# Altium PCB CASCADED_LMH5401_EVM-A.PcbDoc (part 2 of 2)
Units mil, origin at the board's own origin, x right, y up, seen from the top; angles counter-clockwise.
Board outline 1606 x 1500 mil, 6 copper layers (Top Layer L1, Layer 2 GND L2, Layer 3 V+ L3, Layer 4 V- L4, Layer 5 GND L5, Bottom Layer L6), stack 56.6 mil thick; 98 components, 31 nets, 225 pads, 397 vias.
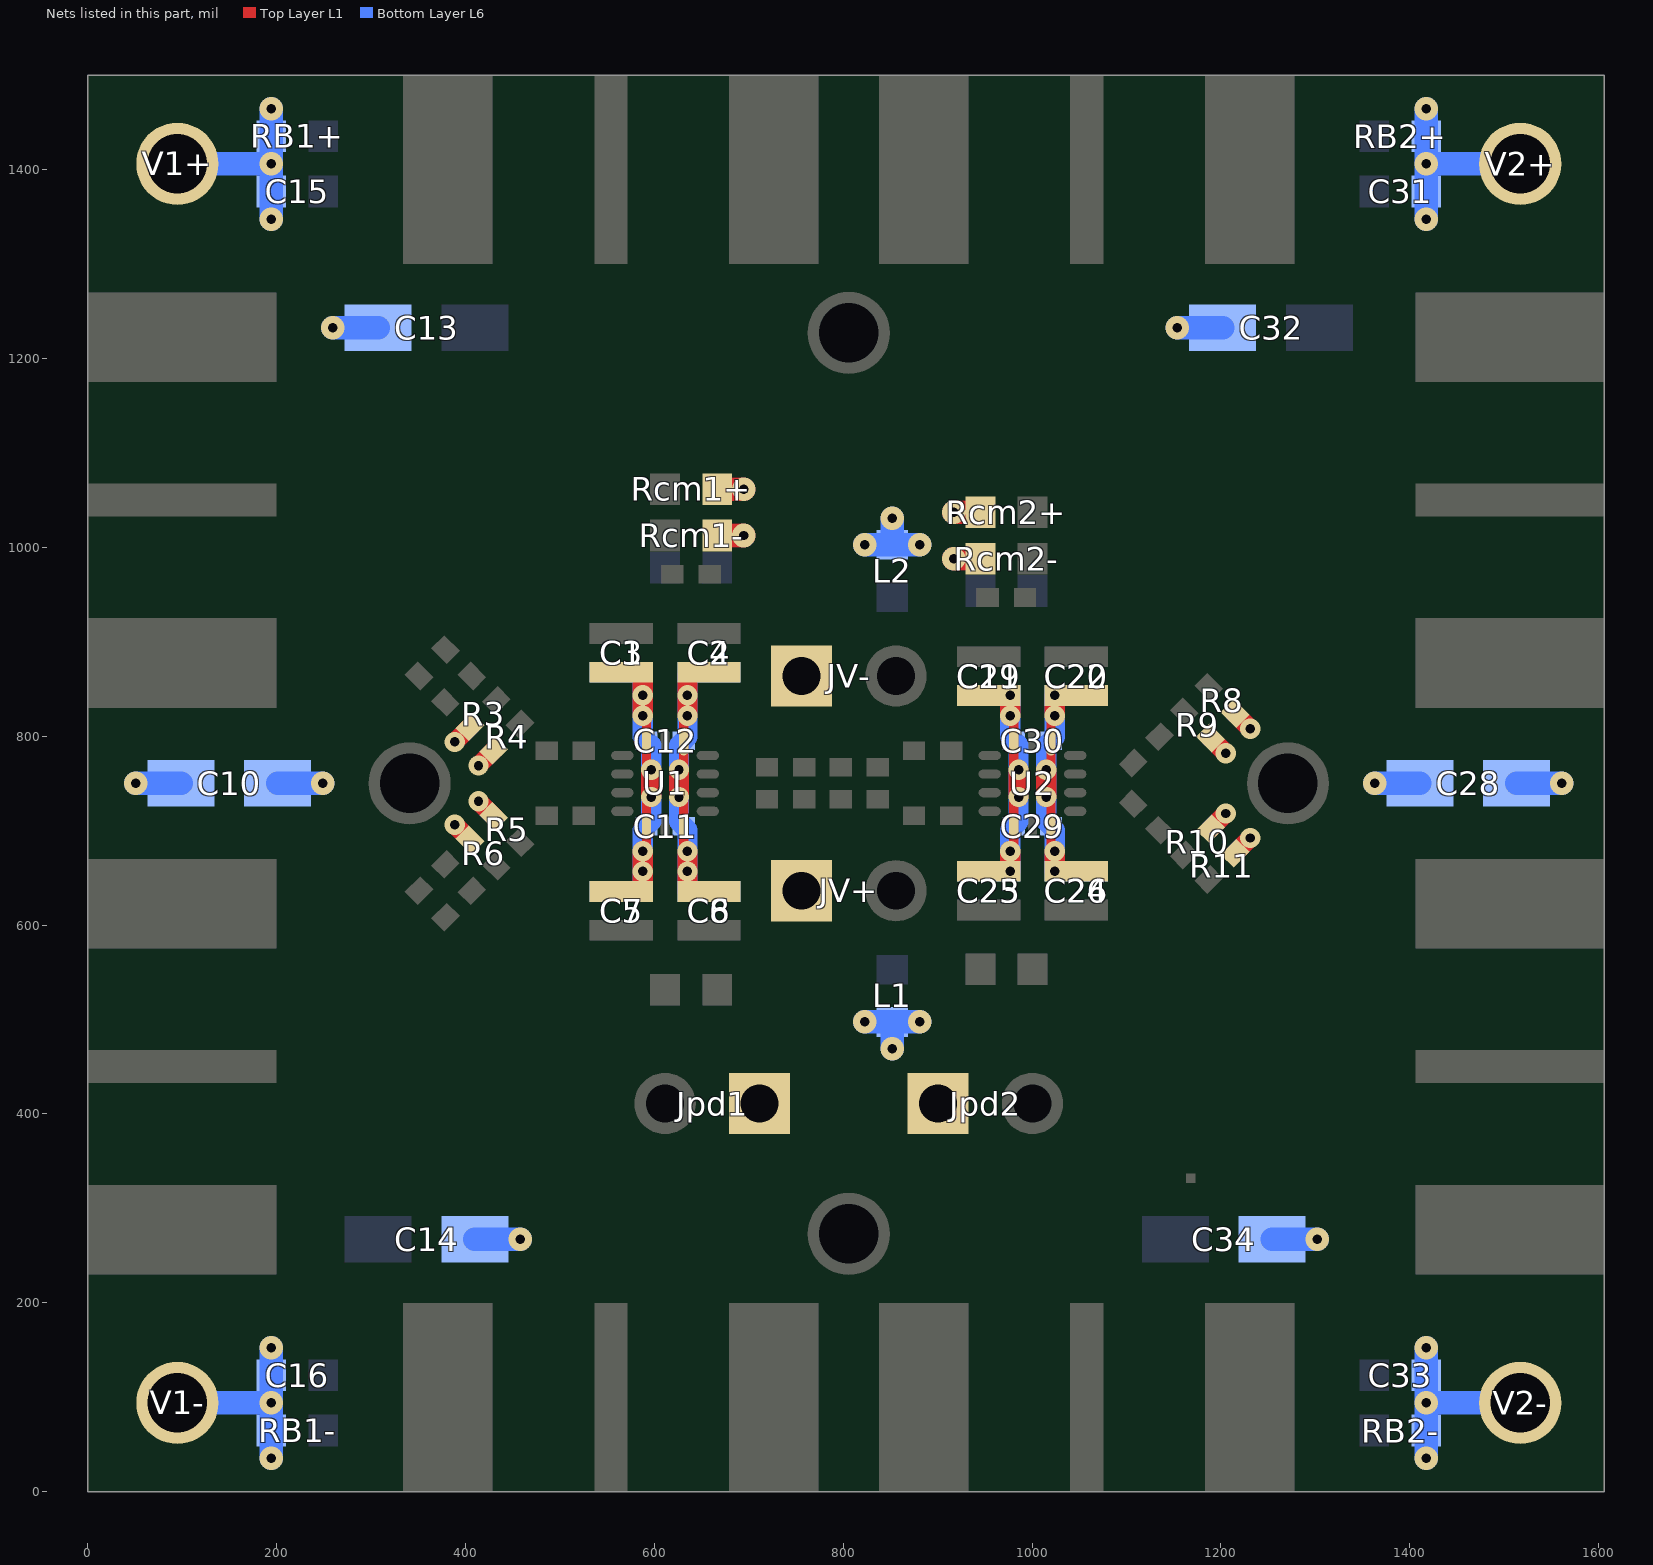
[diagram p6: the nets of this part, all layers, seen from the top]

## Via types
v1: diameter 25, hole 10, Top Layer L1 to Bottom Layer L6, tented both sides, 347 vias
v2: diameter 21.46, hole 10, Top Layer L1 to Bottom Layer L6, tented both sides, 50 vias

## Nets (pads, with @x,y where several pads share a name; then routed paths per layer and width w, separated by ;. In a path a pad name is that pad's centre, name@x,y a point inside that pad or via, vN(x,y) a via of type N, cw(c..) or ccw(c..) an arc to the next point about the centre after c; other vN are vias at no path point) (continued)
V1+: C2.1 C4.2 C6.2 C8.1 C10.1 C11.2 C12.2 C13.1 C15.1 Jpd1.1 JV+.1 R3.2 R6.2 RB1+.2 Rcm1+.2 U1.1 U1.10 V1+.1 | length 950
  Top Layer L1 w9.84: v2(626.17,735.53) 631.13,730.58 U1.10@631.13,704.72 631.13,682.21 v2(635.09,678.24) ; v2(626.17,764.47) 631.13,769.42 631.13,817.79 v2(635.09,821.76)
  Top Layer L1 w19.68: v2(388.8,706.11) R6.2@404.92,689.99 ; v2(388.8,793.89) R3.2@404.92,810.01 ; C6.2@635.09,635.4 C6.2@657.86,635.4 ; C4.2@635.09,867.6 C4.2@657.86,867.6
  Top Layer L1 w21.46: v2(626.17,735.53) v2(626.17,764.47) ; C6.2@635.09,635.32 v2@635.09,656.7 ; v2@635.09,656.86 v2(635.09,678.24) ; v2(635.09,821.76) v2@635.09,843.14 ; v2(635.09,843.22) C4.2@635.09,864.6
  Top Layer L1 w25: Rcm1+.2@666.56,1061.46 v1(694.81,1061.46)
  Bottom Layer L6 w19.68: C8.1@635.09,635.4 C8.1@657.86,635.4 ; C2.1@635.09,867.6 C2.1@657.86,867.6
  Bottom Layer L6 w21.46: C8.1@635.09,635.49 635.09,656.86 v2(635.09,678.24) 635.09,700.76 C11.2@631.13,704.72 626.17,709.68 v2(626.17,735.53) v2(626.17,764.47) 626.17,790.32 C12.2@631.13,795.28 635.09,799.24 v2(635.09,821.76) v2@635.09,843.14 ; v2(635.09,843.22) C2.1@635.09,864.6
  Bottom Layer L6 w25: v1(50.89,750) C10.1@98.82,750 ; V1+.1@95,1406 v1(194.44,1406) ; v1(194.44,1347.54) C15.1@194.44,1376.77 v1(194.44,1406) ; v1(194.44,1464.46) RB1+.2@194.44,1435.23 v1(194.44,1406) ; v1(259.71,1232.5) C13.1@307.65,1232.5
  other v2: 635.09,656.78
V1-: C1.2 C3.1 C5.1 C7.2 C10.2 C11.1 C12.1 C14.2 C16.1 JV-.1 R4.1 R5.1 RB1-.1 Rcm1-.1 U1.3 U1.8 V1-.1 | length 950
  Top Layer L1 w9.84: v2(587.79,678.24) 591.76,682.21 U1.8@591.76,704.72 591.76,730.58 v2(596.71,735.53) ; v2(587.79,821.76) 591.76,817.79 U1.3@591.76,795.28 591.76,769.42 v2(596.71,764.47)
  Top Layer L1 w19.68: v2(413.85,731.15) R5.1@429.96,715.03 ; v2(413.85,768.85) R4.1@429.96,784.97 ; C5.1@565.02,635.4 C5.1@587.79,635.4 ; C3.1@565.02,867.6 C3.1@587.79,867.6
  Top Layer L1 w21.46: C5.1@587.79,635.32 v2@587.79,656.7 ; v2@587.79,656.86 v2(587.79,678.24) ; v2(587.79,821.76) v2@587.79,843.14 ; v2(587.79,843.22) C3.1@587.79,864.6 ; v2(596.71,735.53) v2(596.71,764.47)
  Top Layer L1 w25: Rcm1-.1@666.56,1012.46 v1(694.81,1012.46)
  Bottom Layer L6 w19.68: C7.2@565.02,635.4 C7.2@587.79,635.4 ; C1.2@565.02,867.6 C1.2@587.79,867.6
  Bottom Layer L6 w21.46: C7.2@587.79,635.49 587.79,656.86 v2(587.79,678.24) 587.79,700.76 C11.1@591.76,704.72 596.71,709.68 v2(596.71,735.53) v2(596.71,764.47) 596.71,790.32 C12.1@591.76,795.28 587.79,799.24 v2(587.79,821.76) v2@587.79,843.14 ; v2(587.79,843.22) C1.2@587.79,864.6
  Bottom Layer L6 w25: V1-.1@95,94 v1(194.44,94) ; v1(194.44,35.54) RB1-.1@194.44,64.77 v1(194.44,94) ; v1(194.44,152.46) C16.1@194.44,123.23 v1(194.44,94) ; C10.2@201.18,750 v1(249.11,750) ; C14.2@410.01,267.5 v1(457.94,267.5)
  other v2: 587.79,656.78
V2+: C20.1 C22.2 C24.2 C26.1 C28.1 C29.2 C30.2 C31.1 C32.1 Jpd2.1 L1.2 R9.2 R10.2 RB2+.2 Rcm2+.2 U2.1 U2.10 V2+.1 | length 951.2
  Top Layer L1 w9.84: v2(1015.17,735.53) 1020.13,730.58 U2.10@1020.13,704.72 1020.13,682.21 v2(1024.09,678.24) ; v2(1015.17,764.47) 1020.13,769.42 1020.13,795.28 1020.13,817.79 v2(1024.09,821.76)
  Top Layer L1 w19.68: C24.2@1024.09,656.86 C24.2@1046.86,656.86 ; C22.2@1024.09,843.14 C22.2@1046.86,843.14 ; R10.2@1188.97,702.03 v2(1205.08,718.14) ; R9.2@1188.96,797.97 v2(1205.08,781.86)
  Top Layer L1 w21.46: v2(1015.17,735.53) v2(1015.17,764.47) ; C24.2@1024.09,656.86 v2(1024.09,678.24) ; v2(1024.09,821.76) C22.2@1024.09,843.14
  Top Layer L1 w25: v1(917.07,1037) Rcm2+.2@945.32,1037
  Bottom Layer L6 w19.68: C26.1@1024.09,656.86 C26.1@1046.86,656.86 ; C20.1@1024.09,843.14 C20.1@1046.86,843.14
  Bottom Layer L6 w21.46: C26.1@1024.09,656.86 v2(1024.09,678.24) 1024.09,700.76 C29.2@1020.13,704.72 1015.17,709.68 v2(1015.17,735.53) v2(1015.17,764.47) 1015.17,790.32 C30.2@1020.13,795.28 1024.09,799.24 v2(1024.09,821.76) C20.1@1024.09,843.14
  Bottom Layer L6 w25: v1(822.77,497.44) L1.2@852,497.44 ; v1@852.06,469.19 L1.2@852,497.44 ; v1(881.23,497.44) L1.2@852,497.44 ; v1(1153.94,1232.5) C32.1@1201.87,1232.5 ; v1(1362.77,750) C28.1@1410.7,750 ; v1(1417.44,1347.54) C31.1@1417.44,1376.77 v1(1417.44,1406) ; v1(1417.44,1464.46) RB2+.2@1417.44,1435.23 v1(1417.44,1406) ; V2+.1@1516.88,1406 v1(1417.44,1406)
  other v1: 852,469.19
  other v2: 1024.09,656.78 1024.09,843.22
V2-: C19.2 C21.1 C23.1 C25.2 C28.2 C29.1 C30.1 C33.1 C34.2 L2.2 R8.1 R11.1 RB2-.1 Rcm2-.1 U2.3 U2.8 V2-.1 | length 951.2
  Top Layer L1 w9.84: v2(976.79,678.24) 980.76,682.21 U2.8@980.76,704.72 980.76,730.58 v2(985.71,735.53) ; v2(976.79,821.76) 980.76,817.79 U2.3@980.76,795.28 980.76,769.42 v2(985.71,764.47)
  Top Layer L1 w19.68: C23.1@954.02,656.86 C23.1@976.79,656.86 ; C21.1@954.02,843.14 C21.1@976.79,843.14 ; R11.1@1214.92,676.07 v2(1231.04,692.19) ; R8.1@1214.92,823.93 v2(1231.04,807.81)
  Top Layer L1 w21.46: C23.1@976.79,656.86 v2(976.79,678.24) ; v2(976.79,821.76) C21.1@976.79,843.14 ; v2(985.71,735.53) v2(985.71,764.47)
  Top Layer L1 w25: v1(917.07,988) Rcm2-.1@945.32,988
  Bottom Layer L6 w19.68: C25.2@954.02,656.86 C25.2@976.79,656.86 ; C19.2@954.02,843.14 C19.2@976.79,843.14
  Bottom Layer L6 w21.46: C25.2@976.79,656.86 v2(976.79,678.24) 976.79,700.76 C29.1@980.76,704.72 985.71,709.68 v2(985.71,735.53) v2(985.71,764.47) 985.71,790.32 C30.1@980.76,795.28 976.79,799.24 v2(976.79,821.76) C19.2@976.79,843.14
  Bottom Layer L6 w25: v1(822.77,1002.56) L2.2@852,1002.56 ; v1@851.94,1030.81 L2.2@852,1002.56 ; v1(881.23,1002.56) L2.2@852,1002.56 ; C34.2@1254.24,267.5 v1(1302.17,267.5) ; v1(1417.44,35.54) RB2-.1@1417.44,64.77 v1(1417.44,94) ; v1(1417.44,152.46) C33.1@1417.44,123.23 v1(1417.44,94) ; C28.2@1513.06,750 v1(1561,750) ; V2-.1@1516.88,94 v1(1417.44,94)
  other v1: 852,1030.81
  other v2: 976.79,656.78 976.79,843.22

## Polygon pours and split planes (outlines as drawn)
GND on Top Layer L1 "Top Layer L1-GND" (solid, remove dead copper, pour order 3): 0,0 0,1500 1606,1500 1606,0
GND on Bottom Layer L6 "Bottom Layer L6-GND" (solid, remove dead copper, pour order 4): 0,0 0,1500 1606,1500 1606,0
GND on Layer 2 GND L2 (split plane): 1605.95,0.05 0.05,0.05 0.05,1499.95 1605.95,1499.95
V2+ on Layer 3 V+ L3 (split plane): 1585.9,20.1 818.5,20.1 818.5,461.06 818.26,463.51 817.55,465.87 816.38,468.04 814.82,469.94 797.56,487.2 797.56,507.68 814.82,524.94 816.38,526.84 817.55,529.02 818.26,531.37 818.5,533.82 818.5,966.18 818.26,968.63 817.55,970.98 816.38,973.16 814.82,975.06 797.56,992.32 797.56,1012.8 814.82,1030.06 816.38,1031.96 817.55,1034.13 818.26,1036.49 818.5,1038.94 818.5,1479.9 1585.9,1479.9
V1+ on Layer 3 V+ L3 (split plane): 793.38,1044.14 776.12,1026.88 774.56,1024.98 773.4,1022.81 772.68,1020.45 772.44,1018 772.44,987.12 772.68,984.67 773.4,982.31 774.56,980.14 776.12,978.24 793.38,960.97 793.38,539.03 776.12,521.76 774.56,519.86 773.4,517.69 772.68,515.33 772.44,512.88 772.44,482 772.68,479.55 773.4,477.19 774.56,475.02 776.12,473.12 793.38,455.86 793.38,20.1 20.1,20.1 20.1,1479.9 793.38,1479.9
V2- on Layer 4 V- L4 (split plane): 1585.9,20.1 818.5,20.1 818.5,461.06 818.26,463.51 817.55,465.87 816.38,468.04 814.82,469.94 797.56,487.2 797.56,507.68 814.82,524.94 816.38,526.84 817.55,529.02 818.26,531.37 818.5,533.82 818.5,966.18 818.26,968.63 817.55,970.98 816.38,973.16 814.82,975.06 797.56,992.32 797.56,1012.8 814.82,1030.06 816.38,1031.96 817.55,1034.13 818.26,1036.49 818.5,1038.94 818.5,1479.9 1585.9,1479.9
V1- on Layer 4 V- L4 (split plane): 793.38,1044.14 776.12,1026.88 774.56,1024.98 773.4,1022.81 772.68,1020.45 772.44,1018 772.44,987.12 772.68,984.67 773.4,982.31 774.56,980.14 776.12,978.24 793.38,960.97 793.38,539.03 776.12,521.76 774.56,519.86 773.4,517.69 772.68,515.33 772.44,512.88 772.44,482 772.68,479.55 773.4,477.19 774.56,475.02 776.12,473.12 793.38,455.86 793.38,20.1 20.1,20.1 20.1,1479.9 793.38,1479.9
GND on Layer 5 GND L5 (split plane): 1605.95,0.05 0.05,0.05 0.05,1499.95 1605.95,1499.95

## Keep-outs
Keep-Out Layer:
  text ".Layer_Name" at 577,-858.49 h60

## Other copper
Top Layer L1:
  pour cut-out: 491,811 408.27,893.73 371.27,856.73 461.36,766.64 460.61,732.61 371.27,643.27 408.27,606.27 491,689 672,689 672,811
  pour cut-out: 1120.88,811 1203.61,893.73 1240.61,856.73 1139.93,756.05 1140.21,743.67 1240.61,643.27 1203.61,606.27 1120.88,689 939.88,689 939.88,811
  text ".Layer_Name" at 577,-858.49 h60
Bottom Layer L6:
  text ".Layer_Name" at 577,-858.49 h60
Layer 2 GND L2 (plane layer: these items are gaps in the copper):
  text ".Layer_Name" at 577,-858.49 h60
Layer 3 V+ L3 (plane layer: these items are gaps in the copper):
  lines w25: 805.94,0 805.94,461.06 785,482 785,512.88 805.94,533.82 805.94,966.18 785,987.12 785,1018 805.94,1038.94 805.94,1500
  text ".Layer_Name" at 577,-858.49 h60
Layer 4 V- L4 (plane layer: these items are gaps in the copper):
  lines w10: 0,1500 1606,1500
  lines w25: 805.94,0 805.94,461.06 785,482 785,512.88 805.94,533.82 805.94,966.18 785,987.12 785,1018 805.94,1038.94 805.94,1500
  text ".Layer_Name" at 577,-858.49 h60
Layer 5 GND L5 (plane layer: these items are gaps in the copper):
  text ".Layer_Name" at 577,-858.49 h60

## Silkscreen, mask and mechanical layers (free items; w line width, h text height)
Top Overlay:
  lines w10: 806.23,586 806.23,704 ; 808.23,795 808.23,1014
  text ".PRJ_Title" at 238,327 h40
  text ".Layer_Name" at 577,-858.49 h60
Bottom Overlay:
  text ".Layer_Name" at 577,-858.49 h60
Top Paste:
  text ".Layer_Name" at 577,-858.49 h60
Bottom Paste:
  text ".Layer_Name" at 577,-858.49 h60
Top Solder:
  lines w9.84: 875.08,717.08 898.16,740.16 955.17,740.16 ; 875.08,782.92 898.16,759.84 955.17,759.84
  lines w10.84: 486.08,717.08 509.16,740.16 566.17,740.16 ; 486.08,782.92 509.16,759.84 566.17,759.84 ; 875.08,717.08 898.16,740.16 955.17,740.16 ; 875.08,782.92 898.16,759.84 955.17,759.84
  lines w15.84: 457.8,687.19 486.08,715.47 ; 457.8,812.81 486.08,784.53 ; 486.08,715.55 486.08,717.08 ; 486.08,782.92 486.08,784.45 ; 656.72,740.16 712.16,740.16 719.32,733 ; 656.72,759.84 712.16,759.84 719.32,767 ; 758.69,733 797.31,733 ; 758.69,767 797.32,767 ; 836.68,733 859.16,733 875.08,717.08 ; 836.69,767 859.16,767 875.08,782.92 ; 1045.72,740.16 1095.16,740.16 1107.01,728.31 ; 1045.72,759.84 1095.16,759.84 1107.01,771.69
  lines w24.68: 1134.85,700.47 1161.13,674.19 ; 1134.85,799.53 1161.13,825.81
  lines w25.68: 350.92,636.4 378.96,608.35 ; 350.92,863.6 378.96,891.65 ; 406.8,636.19 432.76,662.15 457.8,687.19 ; 406.8,863.81 432.76,837.85 457.8,812.81 ; 1161.13,674.19 1187.08,648.23 ; 1161.13,825.81 1187.08,851.77
  lines w41: 100,450 220.61,450 374.89,604.29 ; 100,1050 220.61,1050 374.89,895.71 ; 1187.08,648.23 1385.32,450 1506,450 ; 1187.08,851.77 1385.32,1050 1506,1050
  text ".Layer_Name" at 577,-858.49 h60
  text ".Layer_Name" at 577,-858.49 h60
Bottom Solder:
  text ".Layer_Name" at 577,-858.49 h60
Drill Guide:
  text ".Layer_Name" at 577,-858.49 h60
M1 Board Outline:
  the board outline again, w10
  text ".Layer_Name" at 577,-858.49 h60
M2 Board Dimensions:
  rectangle: -0.5,-285.5 124.5,-160.5
  rectangle: 124.5,-410.5 499.5,-285.5
  lines w7: -0.5,-285.5 999.5,-285.5 ; 124.5,-410.5 124.5,-160.5 ; 249.5,-410.5 249.5,-160.5 ; 499.5,-410.5 499.5,-160.5 ; 749.5,-410.5 749.5,-160.5 ; -0.5,-410.5 999.5,-410.5 999.5,-160.5 -0.5,-160.5 -0.5,-410.5
  lines w10: -0.5,-475.5 -0.5,-455.5 ; 59.5,-485.5 -0.5,-465.5 ; 59.5,-445.5 -0.5,-465.5 ; 223.58,-465.5 -0.5,-465.5 ; 775.42,-465.5 999.5,-465.5 ; 939.5,-485.5 999.5,-465.5 ; 939.5,-445.5 999.5,-465.5 ; 999.5,-475.5 999.5,-455.5
  text "1000 (mil)" at 233.58,-501.49 h60
  text ".Layer_Name" at 577,-858.49 h60
M3 3D STEP Top:
  text ".Layer_Name" at 577,-858.49 h60
M4 3D STEP Bottom:
  text ".Layer_Name" at 577,-858.49 h60
M5 Assembly Top:
  lines w10: -292,-930.17 6308,-930.17 ; -292,-726.83 6310,-726.83 ; -292,-523.5 -292,-1133.5 3713,-1133.5 6310,-1133.5 6310,-523.5 -291.5,-523.5 -291.5,-1133.5 1284,-1133.5 ; 2173,-1133.5 2173,-523.5 ; 3440,-726.83 3440,-523.5 ; 4280,-726.83 4280,-523.5 ; 4902,-1140 4902,-937.17
  text "COMPONENTS MARKED 'DNP' SHOULD NOT BE POPULATED." at 1153.5,-318.5 h60
  text "ASSEMBLY VARIANT:" at 1153,-434 h60
  text ".VariantName" at 2189,-434 h60
  text "PCB VIEWED FROM TOP SIDE" at -228.5,-655.67 h60
  text "BOARD #:" at 2248,-655.67 h60
  text ".PRJ_Number" at 2793.5,-655.67 h60
  text "REV:" at 3638,-655.67 h60
  text ".PCB_Rev" at 3929.5,-655.67 h60
  text "SVN REV:" at 4476,-655.67 h60
  text ".VersionControl_RevNumber" at 4982,-655.67 h60
  text "IGNORE ->" at -228.5,-858.49 h60
  text "PLOT NAME =" at -228.5,-1064.34 h60
  text ".plot_File_Name" at 577,-1064.34 h60
  text "GENERATED    :" at 2250,-1064.34 h60
  text ".Print_Date" at 3119.5,-1064.34 h60
  text ".Print_Time" at 3848.5,-1064.34 h60
  text "TEXAS INSTRUMENTS" at 5113,-1064.34 h60
M6 Assembly Bottom:
  lines w10: -292.5,-727.33 6309.5,-727.33 ; -290.5,-930.67 6309.5,-930.67 ; 1115.5,-1140.5 1115.5,-937.67 ; 1737.5,-727.33 1737.5,-524 ; 2577.5,-727.33 2577.5,-524 ; 3844.5,-1134 3844.5,-524 ; 4733.5,-1134 6309,-1134 6309,-524 -292.5,-524 -292.5,-1134 2304.5,-1134 6309.5,-1134 6309.5,-524
  text "COMPONENTS MARKED 'DNP' SHOULD NOT BE POPULATED." at 6102,-318 h60
  text ".VariantName" at 5058,-434 h60
  text "ASSEMBLY VARIANT:" at 6097,-434 h60
  text ".VersionControl_RevNumber" at 1035.5,-656.17 h60
  text "SVN REV:" at 1541.5,-656.17 h60
  text ".PCB_Rev" at 2088,-656.17 h60
  text "REV:" at 2379.5,-656.17 h60
  text ".PRJ_Number" at 3224,-656.17 h60
  text "BOARD #:" at 3769.5,-656.17 h60
  text "PCB VIEWED FROM BOTTOM SIDE" at 6246,-656.17 h60
  text "IGNORE ->" at 2547.85,-858.49 h60
  text "TEXAS INSTRUMENTS" at 904.5,-1064.84 h60
  text ".Print_Time" at 2169,-1064.84 h60
  text ".Print_Date" at 2898,-1064.84 h60
  text "GENERATED    :" at 3767.5,-1064.84 h60
  text ".plot_File_Name" at 5440.5,-1064.84 h60
  text "PLOT NAME =" at 6246,-1064.84 h60
M9 Title Sheet:
  drawing of 57 lines, arcs and shapes, not listed
  text "1" at 739.84,8036.5 h70
  text "2" at 3235.5,8036.5 h70
  text "3" at 5724.84,8036.5 h70
  text "4" at 8231.51,8036.5 h70
  text "5" at 10730.5,8036.5 h70
  text "6" at 13235.5,8036.5 h70
  text "A" at -416.5,6893.5 h70
  text "A" at 14383.5,6893.5 h70
  text "B" at -416.5,4513.5 h70
  text "B" at 14383.5,4513.5 h70
  text "C" at -416.5,2138.5 h70
  text "C" at 14383.5,2138.5 h70
  text "PROJECT TITLE:" at 11343.5,277.5 h45
  text ".PRJ_Title" at 11393.5,144.17 h70
  text "DESIGNED FOR:" at 11343.5,-23.5 h45
  text ".PRJ_Customer" at 11393.5,-163.5 h70
  text "D" at -416.5,-231.5 h70
  text "D" at 14383.5,-231.5 h70
  text "FILE NAME:" at 11343.5,-323.5 h45
  text ".PCB_File_Name_No_Path" at 11393.5,-443.5 h70
  text "Texas Instruments (TI) and/or its licensors do not warrant the accuracy or completeness of this specification" at 6374,-605.34 h45
  text "ENGINEER:" at 11343.5,-613.5 h45
  text "LAYOUT BY:" at 12848.5,-613.5 h45
  text "or any information contained therein. TI and/or its licensors do not warrant that this design will meet" at 6329.01,-718 h45
  text ".PRJ_Engineer" at 11393.5,-768.49 h70
  text ".PCB_Layout" at 12899,-768.49 h70
  text "the specifications, will be suitable for your application or fit for any particular purpose, or will operate in" at 6329.01,-830.67 h45
  text ".Layer_Name" at 577,-858.49 h60
  text "ALTIUM DESIGNER VERSION:" at 12848.5,-923.5 h45
  text "an implementation. TI and/or its licensors do not warrant that the design is production worthy. You should" at 6329.01,-943.33 h45
  text "completely validate and test your design implementation to confirm the system functionality for your application." at 6374,-1056 h45
  text ".print_Scale" at 11393.5,-1056.83 h70
  text ".Application_BuildNumber" at 12899,-1056.83 h70
  text "1" at 739.84,-1263.5 h70
  text "2" at 3235.5,-1263.5 h70
  text "3" at 5724.84,-1263.5 h70
  text "4" at 8231.51,-1263.5 h70
  text "5" at 10730.5,-1263.5 h70
  text "6" at 13235.5,-1263.5 h70
M10 Fab Notes:
  drawing of 212 lines, arcs and shapes, not listed
  text "DESIGN INFORMATION" at 12381.02,6810 h60
  text "(REFER ALSO ARRAY/PANEL PROFILING INFORMATION)" at 12019.46,6648.29 h60
  text "BOARD SIZE" at 11333.46,6644 h60
  text "X" at 12301.46,6516.18 h60
  text "Number of Layers :" at 11736.46,6319 h60
  text "6" at 12831.27,6309 h60
  text "MIN. TRACK WIDTH:" at 11736.46,6180 h60
  text "8" at 12832.7,6180 h60
  text "MIL" at 12987.46,6180 h60
  text "MIN. CLEARANCE:" at 11736.46,6048 h60
  text "8" at 12832.7,6048 h60
  text "MIL" at 12987.46,6048 h60
  text "MIN. VIA PAD SIZE:" at 11736.46,5916 h60
  text "21" at 12802.71,5916 h60
  text "MIL" at 12987.46,5916 h60
  text "0.05mm (2MIL)" at 12431.46,5774.29 h60
  text "MINIMUM ANNULAR RING" at 11407.23,5770 h60
  text "EXTERNAL" at 13139.46,5770 h60
  text "PER" at 11607.23,5652 h60
  text "IPC-D-275 CLASS 2 LEVEL C" at 11827.23,5652 h60
  text "MIL, HOLES" at 13315.46,5539.71 h60
  text "+/-" at 12923,5539 h60
  text "+/-" at 13777,5539 h60
  text "REGISTRATION TOLERANCES:" at 11407.23,5534 h60
  text "METAL" at 12607,5534 h60
  text "5" at 13183.2,5534 h60
  text "3" at 14016.2,5534 h60
  text "MIL" at 14132.46,5534 h60
  text "MATERIAL:" at 11332.46,5324.54 h60
  text "FR-4 High Tg" at 12318.9,5184.21 h60
  text "FR-408" at 11753.46,5175.64 h60
  text "X" at 12165.46,5175.64 h60
  text "X" at 13054.46,5176 h60
  text "OTHER" at 13241.46,5175.64 h60
  text "OTHER   ROGERS 4350" at 13241.46,5175.64 h60
  text "62 MIL (1.6mm) +/-10%" at 12073.56,5012.92 h60
  text "THICKNESS:" at 11407.23,5008.64 h60
  text "X" at 11945.4,5008.64 h60
  text "OTHER" at 13358.46,5008.64 h60
  text "TOLERANCE:" at 11407.23,4850.64 h60
  text "X" at 12246.53,4850.64 h60
  text "ANSI IPC-6012 TYPE 3 CLASS 2" at 12433.48,4850.64 h60
  text "OTHER +/-" at 12433.46,4694.64 h60
  text "BOW & TWIST:" at 11407.23,4537.64 h60
  text "X" at 12246.53,4537.64 h60
  text "ANSI IPC-6012 TYPE 3 CLASS 2" at 12433.48,4537.64 h60
  text "OTHER +/-" at 12433.46,4379.13 h60
  text "COPPER THICKNESS (FINISHED):" at 11332.46,4243.64 h60
  text "1.4MIL (1oz)" at 12212.46,4090.92 h60
  text "2MIL (1.4oz)" at 12979.46,4090.92 h60
  text "2.8MIL (2oz)" at 13706.46,4090.92 h60
  text "OUTER:" at 11689.46,4086.64 h60
  text "X" at 12084,4086 h60
  text "1.4MIL (1oz)" at 12212.46,3933.92 h60
  text "2.8MIL (2oz)" at 12979.46,3933.92 h60
  text "N/A" at 13706,3934.29 h60
  text "INNER SIGNAL:" at 11400.38,3929.64 h60
  text "X" at 12085.42,3929.64 h60
  text "DRILLING:" at 11332.46,3790.64 h60
  text "REFERENCE:" at 11407.23,3673.64 h60
  text "X" at 12055.46,3673.64 h60
  text "AS SHOWN" at 12242.46,3673.64 h60
  text "X" at 12956.46,3673.64 h60
  text "NC_DRILL FILES" at 13093.46,3673.64 h60
  text "PTH MIN COPPER THICKNESS:" at 11407.23,3515.64 h60
  text "X" at 12757.46,3515.64 h60
  text "1MIL" at 12894.46,3515.64 h60
  text "OTHER" at 13391.46,3515.64 h60
  text "BOARD FINISH:" at 11332.46,3356.64 h60
  text "SILKSCREEN:" at 11487.68,3238.64 h60
  text "X" at 12436.46,3238.64 h60
  text "TOP" at 12562.46,3238.64 h60
  text "X" at 12946.46,3238.64 h60
  text "BOTTOM" at 13073.46,3238.64 h60
  text "SILKSCREEN COLOR:" at 11487.68,3071.64 h60
  text "X" at 12435.42,3071.64 h60
  text "WHITE" at 12562.46,3071.64 h60
  text "OTHER" at 13073.46,3071.64 h60
  text "SOLDER RESIST COLOR:" at 11487.68,2901.64 h60
  text "X" at 12055.42,2742.44 h60
  text "GREEN" at 12182.46,2742.44 h60
  text "BLUE" at 12773.46,2742.44 h60
  text "OTHER" at 13311.46,2742.44 h60
  text "IMMERSION GOLD (ENIG)" at 12393.46,2553.92 h60
  text "ENEPIG" at 13731,2550.64 h60
  text "SURFACE FINISH:" at 11332.46,2549.64 h60
  text "X" at 12206.51,2549.64 h60
  text "IMM. TIN/SILVER OR EQUIV" at 11662,2392.64 h60
  text "OTHER" at 13093.46,2392.64 h60
  text "ARRAY/PANEL:" at 11332.46,2213.64 h60
  text "X" at 12206.46,2213.64 h60
  text "CUT AND TRIM PER MECH LAYER 1" at 12393.46,2209.35 h60
  text "N.C. ROUTE" at 12393.46,2057.64 h60
  text "V. SCORE" at 13259.46,2057.64 h60
  text "CERTIFICATION:" at 11332.46,1920.64 h60
  text "MATERIALS AND WORKMANSHIP FOR ALL PCBS" at 12057.46,1920.64 h60
  text "TO MEET OR EXCEED THE REQUIREMENTS OF:" at 12057.46,1822.64 h60
  text "X" at 11683.96,1686.13 h60
  text "ANSI IPC-A-600F CLASS ->" at 11822.96,1686.13 h60
  text "X" at 13462.02,1686.13 h60
  text "2" at 13580.96,1686.14 h60
  text "1" at 13265.96,1684.64 h60
  text "3" at 13934.96,1684.64 h60
  text "X" at 11686.02,1526.64 h60
  text "UL 94V-0" at 11822.96,1526.64 h60
  text "X" at 12498.02,1526.64 h60
  text "RoHS" at 12634.96,1526.64 h60
  text "OTHER" at 13279.36,1526.64 h60
  text "PER ORDER" at 13676.42,1526.64 h60
  text "Single ended tracks 50 ohms Top Layer equal 35mils width." at 2594,1500 h100
  text "ADDITIONAL REQUIREMENTS:" at 11332.46,1385.64 h60
  text "MICROSECTION:" at 11407.23,1270.64 h60
  text "YES" at 12312.96,1270.64 h60
  text "REQUIRED" at 13174.46,1114.49 h60
  text "BARE BOARD ELEC. TEST:" at 11407.23,1111.64 h60
  text "NONE" at 12712.96,1111.64 h60
  text "X" at 13047.46,1111.64 h60
  text "PER ORDER" at 13766.46,1111.64 h60
  text "MANUFACTURER'S UL:" at 11407.23,954.64 h60
  text "RAIL" at 12572.96,950.35 h60
  text "METAL" at 13064.77,950.35 h60
  text "X" at 13440,950 h60
  text "SILK" at 13576.46,950.35 h60
  text ".Layer_Name" at 577,-858.49 h60
M11 Gerber Information:
  lines w10: -292,-930.17 6308,-930.17 ; -292,-726.83 6310,-726.83 ; -292,-523.5 -292,-1133.5 3713,-1133.5 6310,-1133.5 6310,-523.5 -291.5,-523.5 -291.5,-1133.5 1284,-1133.5 ; 2173,-1133.5 2173,-523.5 ; 3440,-726.83 3440,-523.5 ; 4280,-726.83 4280,-523.5 ; 4902,-1140 4902,-937.17
  text "ALL ARTWORK VIEWED FROM TOP SIDE" at -228.5,-655.67 h60
  text "BOARD #:" at 2248,-655.67 h60
  text ".PRJ_Number" at 2793.5,-655.67 h60
  text "REV:" at 3638,-655.67 h60
  text ".PCB_Rev" at 3929.5,-655.67 h60
  text "SVN REV:" at 4476,-655.67 h60
  text ".VersionControl_RevNumber" at 4982,-655.67 h60
  text "LAYER NAME =" at -228.5,-858.49 h60
  text "PLOT NAME =" at -228.5,-1064.34 h60
  text ".plot_File_Name" at 577,-1064.34 h60
  text "GENERATED    :" at 2250,-1064.34 h60
  text ".Print_Date" at 3119.5,-1064.34 h60
  text ".Print_Time" at 3848.5,-1064.34 h60
  text "TEXAS INSTRUMENTS" at 5113,-1064.34 h60
M12 Stackup:
  lines w5: 11362,7748.1 14230,7748.1 ; 11362,7843.3 14230,7843.3 ; 11302,6967 ccw(c11333,6967) 11333,6936 14259,6936 ccw(c14259,6967) 14290,6967 14290,7917 ccw(c14259,7917) 14259,7948 11333,7948 ccw(c11333,7917) 11302,7917 11302,6967
  text "Layer Stack Up Detail for: CASCADED_LMH5401_EVM-A.PcbDoc" at 11362,7866.15 h40
  text "Layer" at 11362,7807.8 h22
  text "Gerber" at 11973.83,7807.8 h22
  text "Copper" at 12285.82,7807.8 h22
  text "Dielectric" at 12633.74,7807.8 h22
  text "Dielectric" at 12997.05,7807.8 h22
  text "Dielectric" at 13453.93,7807.8 h22
  text "Dielectric" at 13817.24,7807.8 h22
  text "Name" at 11362,7763.8 h22
  text "Document" at 11973.83,7763.8 h22
  text "Thickness" at 12285.82,7763.8 h22
  text "Height" at 12633.74,7763.8 h22
  text "Material" at 12997.05,7763.8 h22
  text "Constant" at 13453.93,7763.8 h22
  text "Type" at 13817.24,7763.8 h22
  text "Top Solder Mask" at 11362,7701.33 h31
  text "(.GTS)" at 11973.83,7701.33 h31
  text "0.4mil" at 12633.74,7701.33 h31
  text "Solder Resist" at 12997.05,7701.33 h31
  text "3.50" at 13453.93,7701.33 h31
  text "Top Layer L1" at 11362,7612.77 h31
  text "(.GTL)" at 11973.83,7612.77 h31
  text "1.4mil" at 12285.82,7612.77 h31
  text "16.6mil" at 12633.74,7568.5 h31
  text "Rogers RO4350" at 12997.05,7568.5 h31
  text "3.66" at 13453.93,7568.5 h31
  text "Core" at 13817.24,7568.5 h31
  text "Layer 2 GND L2" at 11362,7524.23 h31
  text "(.GP1)" at 11973.83,7524.23 h31
  text "1.4mil" at 12285.82,7524.23 h31
  text "5mil" at 12633.74,7479.95 h31
  text "FR406" at 12997.05,7479.95 h31
  text "4.80" at 13453.93,7479.95 h31
  text "PrePreg" at 13817.24,7479.95 h31
  text "Layer 3 V+ L3" at 11362,7435.67 h31
  text "(.GP2)" at 11973.83,7435.67 h31
  text "1.4mil" at 12285.82,7435.67 h31
  text "5mil" at 12633.74,7391.4 h31
  text "FR406" at 12997.05,7391.4 h31
  text "4.80" at 13453.93,7391.4 h31
  text "Core" at 13817.24,7391.4 h31
  text "Layer 4 V- L4" at 11362,7347.12 h31
  text "(.GP3)" at 11973.83,7347.12 h31
  text "1.4mil" at 12285.82,7347.12 h31
  text "5mil" at 12633.74,7302.85 h31
  text "FR406" at 12997.05,7302.85 h31
  text "4.80" at 13453.93,7302.85 h31
  text "PrePreg" at 13817.24,7302.85 h31
  text "Layer 5 GND L5" at 11362,7258.58 h31
  text "(.GP4)" at 11973.83,7258.58 h31
  text "1.4mil" at 12285.82,7258.58 h31
  text "16.6mil" at 12633.74,7214.3 h31
  text "FR406" at 12997.05,7214.3 h31
  text "4.80" at 13453.93,7214.3 h31
  text "Core" at 13817.24,7214.3 h31
  text "Bottom Layer L6" at 11362,7170.02 h31
  text "(.GBL)" at 11973.83,7170.02 h31
  text "1.4mil" at 12285.82,7170.02 h31
  text "Bottom Solder Mask" at 11362,7081.48 h31
  text "(.GBS)" at 11973.83,7081.48 h31
  text "0.4mil" at 12633.74,7081.48 h31
  text "Solder Resist" at 12997.05,7081.48 h31
  text "3.50" at 13453.93,7081.48 h31
  text ".Layer_Name" at 577,-858.49 h60
M13 Component Bodies Top:
  text ".Layer_Name" at 577,-858.49 h60
M14 Component Bodies Bottom:
  text ".Layer_Name" at 577,-858.49 h60
M15 Courtyards Top:
  text ".Layer_Name" at 577,-858.49 h60
M16 Courtyards Bottom:
  text ".Layer_Name" at 577,-858.49 h60
Drill Drawing:
  text ".legend" at 5122.5,725.5 h60
  text "Drill Table" at 5147.5,540.5 h60
  text ".Layer_Name" at 577,-858.49 h60

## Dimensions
0,0 to 0,1500 on M2 Board Dimensions
0,0 to 1606,0 on M2 Board Dimensions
